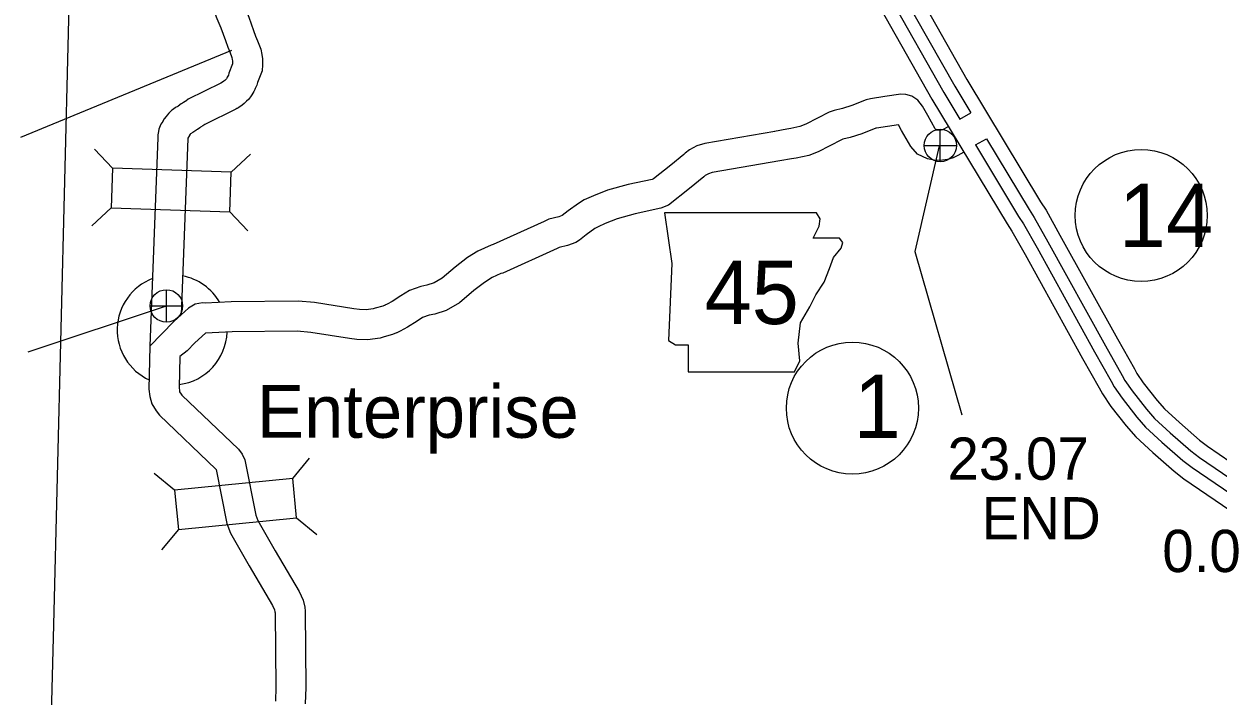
# Model space of a CAD drawing. Extents: x -939622 to -934245, y 1383184 to 1385301.
# Drawn here: x -936449.21 to -936413.38, y 1384508.29 to 1384528.45 of the extents above; entities that cross this region are included whole.
import ezdxf

# ---------------------------------------------------------------- set-up
doc = ezdxf.new("R2010")
doc.units = 0
for name, color, linetype in [('Level 1', 7, 'Continuous'), ('Level 10', 7, 'Continuous'), ('Level 15', 7, 'Continuous'), ('Level 20', 7, 'Continuous'), ('Level 21', 7, 'Continuous'), ('Level 24', 7, 'Continuous'), ('Level 25', 7, 'Continuous'), ('Level 26', 7, 'Continuous'), ('Level 27', 7, 'Continuous')]:
    doc.layers.add(name, color=color, linetype=linetype)

msp = doc.modelspace()

# ---------------------------------------------------------------- linework, layer by layer
at = {"layer": 'Level 1'}
for points in [[(-936448.314, 1384510.423), (-936447.763, 1384532.629)], [(-936449.208, 1384475.592), (-936449.172, 1384477.157), (-936448.921, 1384487.173), (-936448.696, 1384495.463), (-936448.314, 1384510.423)]]:
    msp.add_lwpolyline(points, dxfattribs=at)
at = {"layer": 'Level 10'}
for p, q in [((-936443.206, 1384526.735), (-936443.209, 1384526.732)), ((-936442.664, 1384526.016), (-936442.756, 1384525.946))]:
    msp.add_line(p, q, dxfattribs=at)
for points in [[(-936442.722, 1384529.313), (-936442.581, 1384528.946), (-936442.46, 1384528.649), (-936442.317, 1384528.252), (-936442.257, 1384528.079), (-936442.196, 1384527.944), (-936442.104, 1384527.69), (-936442.069, 1384527.528), (-936442.054, 1384527.4), (-936442.05, 1384527.223), (-936442.064, 1384527.044), (-936442.202, 1384526.693)], [(-936443.59, 1384529.063), (-936443.418, 1384528.615), (-936443.301, 1384528.327), (-936443.165, 1384527.951), (-936443.094, 1384527.747), (-936443.031, 1384527.606), (-936442.97, 1384527.44), (-936442.958, 1384527.382), (-936442.953, 1384527.338), (-936442.951, 1384527.249), (-936443.061, 1384526.967)], [(-936443.061, 1384526.967), (-936443.074, 1384526.914), (-936443.075, 1384526.913), (-936443.107, 1384526.852), (-936443.117, 1384526.824), (-936443.119, 1384526.821), (-936443.132, 1384526.803), (-936443.175, 1384526.759), (-936443.179, 1384526.755), (-936443.206, 1384526.735)], [(-936443.209, 1384526.732), (-936443.25, 1384526.701), (-936443.296, 1384526.675), (-936443.302, 1384526.671), (-936444.278, 1384526.194), (-936444.355, 1384526.129), (-936444.37, 1384526.12), (-936444.42, 1384526.091), (-936444.449, 1384526.068), (-936444.49, 1384526.048), (-936444.584, 1384525.983), (-936444.594, 1384525.975), (-936444.665, 1384525.943), (-936444.722, 1384525.889), (-936444.767, 1384525.861), (-936444.858, 1384525.775), (-936444.914, 1384525.708), (-936444.943, 1384525.672), (-936444.999, 1384525.602), (-936445.038, 1384525.528), (-936445.043, 1384525.519), (-936445.104, 1384525.439), (-936445.16, 1384525.293), (-936445.171, 1384525.226), (-936445.187, 1384525.123), (-936445.19, 1384525.044), (-936445.427, 1384518.784)], [(-936442.202, 1384526.693), (-936442.223, 1384526.607), (-936442.27, 1384526.511), (-936442.285, 1384526.482), (-936442.309, 1384526.419), (-936442.372, 1384526.319), (-936442.411, 1384526.264), (-936442.468, 1384526.184), (-936442.528, 1384526.134), (-936442.547, 1384526.114), (-936442.602, 1384526.063), (-936442.664, 1384526.016)], [(-936422.904, 1384526.343), (-936423.384, 1384526.272), (-936423.814, 1384526.206), (-936423.938, 1384526.173), (-936424.371, 1384525.998), (-936424.652, 1384525.909), (-936424.902, 1384525.855), (-936425.053, 1384525.798), (-936425.75, 1384525.437), (-936425.926, 1384525.369), (-936426.199, 1384525.309), (-936426.318, 1384525.293), (-936426.689, 1384525.225)], [(-936421.475, 1384525.372), (-936421.608, 1384525.296), (-936421.651, 1384525.276), (-936421.687, 1384525.266), (-936421.733, 1384525.259), (-936421.778, 1384525.257), (-936421.818, 1384525.265), (-936421.846, 1384525.278), (-936421.867, 1384525.301), (-936422.094, 1384525.699), (-936422.252, 1384525.979), (-936422.387, 1384526.158), (-936422.571, 1384526.277), (-936422.75, 1384526.328), (-936422.904, 1384526.343)], [(-936442.756, 1384525.946), (-936442.791, 1384525.925), (-936442.815, 1384525.913), (-936442.818, 1384525.912), (-936442.848, 1384525.891), (-936443.784, 1384525.434), (-936443.837, 1384525.389), (-936443.909, 1384525.347), (-936443.927, 1384525.333), (-936444.003, 1384525.284), (-936444.035, 1384525.268), (-936444.054, 1384525.255), (-936444.136, 1384525.193), (-936444.209, 1384525.148), (-936444.217, 1384525.139), (-936444.241, 1384525.108), (-936444.243, 1384525.106), (-936444.287, 1384525.026), (-936444.29, 1384525.022), (-936444.291, 1384525.012), (-936444.491, 1384519.725)], [(-936422.973, 1384525.424), (-936423.628, 1384525.324), (-936423.652, 1384525.318), (-936424.067, 1384525.151), (-936424.42, 1384525.039), (-936424.645, 1384524.99), (-936424.685, 1384524.974), (-936425.38, 1384524.615), (-936425.665, 1384524.505), (-936426.042, 1384524.422), (-936426.177, 1384524.403), (-936426.526, 1384524.339)], [(-936421.01, 1384524.601), (-936421.19, 1384524.499), (-936421.333, 1384524.43), (-936421.498, 1384524.384), (-936421.647, 1384524.361), (-936421.849, 1384524.353), (-936422.102, 1384524.404), (-936422.399, 1384524.543), (-936422.603, 1384524.775), (-936422.876, 1384525.254), (-936422.973, 1384525.424)], [(-936426.684, 1384525.225), (-936428.783, 1384524.864), (-936429.019, 1384524.787), (-936429.238, 1384524.674), (-936429.366, 1384524.575), (-936429.413, 1384524.528), (-936429.804, 1384524.215)], [(-936426.531, 1384524.338), (-936428.565, 1384523.989), (-936428.671, 1384523.954), (-936428.752, 1384523.912), (-936428.768, 1384523.9), (-936428.811, 1384523.857), (-936429.243, 1384523.512)], [(-936429.804, 1384524.215), (-936430.324, 1384523.8), (-936430.363, 1384523.785), (-936431.083, 1384523.631), (-936431.698, 1384523.457), (-936432.116, 1384523.293), (-936432.397, 1384523.168), (-936432.571, 1384523.065), (-936432.882, 1384522.844), (-936433.056, 1384522.703), (-936433.158, 1384522.666), (-936433.463, 1384522.593), (-936433.599, 1384522.523), (-936435.133, 1384521.829), (-936435.189, 1384521.817), (-936435.588, 1384521.632), (-936435.896, 1384521.439), (-936436.273, 1384521.156), (-936436.661, 1384520.821), (-936436.899, 1384520.685), (-936437.117, 1384520.616), (-936437.303, 1384520.574), (-936437.645, 1384520.454), (-936437.897, 1384520.292), (-936438.157, 1384520.124), (-936438.314, 1384520.039), (-936438.379, 1384520.011)], [(-936429.243, 1384523.512), (-936429.866, 1384523.014), (-936430.1, 1384522.921), (-936430.866, 1384522.757), (-936431.411, 1384522.603), (-936431.769, 1384522.463), (-936431.983, 1384522.367), (-936432.08, 1384522.31), (-936432.337, 1384522.127), (-936432.544, 1384521.959), (-936432.655, 1384521.891), (-936432.899, 1384521.803), (-936433.148, 1384521.743), (-936433.208, 1384521.712), (-936434.845, 1384520.972), (-936434.897, 1384520.96), (-936435.158, 1384520.839), (-936435.386, 1384520.696), (-936435.708, 1384520.455), (-936436.138, 1384520.084), (-936436.536, 1384519.855), (-936436.882, 1384519.747), (-936437.053, 1384519.708), (-936437.248, 1384519.639), (-936437.41, 1384519.535), (-936437.698, 1384519.35), (-936437.92, 1384519.229), (-936438.022, 1384519.185)], [(-936438.374, 1384520.013), (-936438.441, 1384519.985), (-936438.666, 1384519.924), (-936438.732, 1384519.901), (-936438.943, 1384519.871), (-936439.14, 1384519.878), (-936439.313, 1384519.901), (-936440.489, 1384520.089), (-936440.978, 1384520.133), (-936442.988, 1384520.112), (-936443.77, 1384520.075), (-936443.851, 1384520.08), (-936444.066, 1384520.042), (-936444.27, 1384519.926), (-936444.707, 1384519.528), (-936445.426, 1384518.784)], [(-936438.028, 1384519.183), (-936438.149, 1384519.132), (-936438.396, 1384519.065), (-936438.516, 1384519.022), (-936438.897, 1384518.969), (-936439.216, 1384518.98), (-936439.443, 1384519.01), (-936440.6, 1384519.195), (-936441.013, 1384519.232), (-936442.962, 1384519.212), (-936443.758, 1384519.175), (-936444.08, 1384518.882), (-936444.307, 1384518.647), (-936444.533, 1384518.47)], [(-936445.426, 1384518.784), (-936445.456, 1384517.497), (-936445.43, 1384517.274), (-936445.37, 1384517.056), (-936445.239, 1384516.842), (-936445.145, 1384516.716), (-936443.446, 1384515.098), (-936443.438, 1384515.087), (-936443.12, 1384513.467), (-936443.008, 1384513.173), (-936442.451, 1384512.197), (-936441.748, 1384511.003), (-936441.688, 1384510.875), (-936441.676, 1384510.817), (-936441.673, 1384510.787), (-936441.655, 1384508.554)], [(-936444.533, 1384518.47), (-936444.555, 1384517.54), (-936444.544, 1384517.445), (-936444.536, 1384517.417), (-936444.493, 1384517.347), (-936444.468, 1384517.314), (-936442.768, 1384515.695), (-936442.658, 1384515.546), (-936442.578, 1384515.377), (-936442.252, 1384513.716), (-936442.192, 1384513.558), (-936441.673, 1384512.649), (-936440.952, 1384511.425), (-936440.828, 1384511.163), (-936440.785, 1384510.955), (-936440.773, 1384510.838), (-936440.755, 1384508.547)], [(-936441.655, 1384508.554), (-936441.665, 1384508.14)], [(-936440.755, 1384508.547), (-936440.766, 1384508.053)]]:
    msp.add_lwpolyline(points, dxfattribs=at)
at = {"layer": 'Level 15'}
for points in [[(-936430.838, 1384544.304), (-936420.923, 1384526.779)], [(-936431.586, 1384543.189), (-936421.967, 1384526.188)], [(-936422.878, 1384529.398), (-936421.282, 1384526.576)], [(-936423.222, 1384529.243), (-936421.608, 1384526.392)], [(-936421.282, 1384526.576), (-936420.8, 1384525.777)], [(-936420.923, 1384526.779), (-936418.709, 1384523.107), (-936418.546, 1384522.86), (-936418.127, 1384522.112), (-936416.404, 1384518.999), (-936415.894, 1384518.104), (-936415.824, 1384517.967), (-936415.632, 1384517.688), (-936415.216, 1384517.158), (-936414.992, 1384516.903), (-936414.545, 1384516.491), (-936413.94, 1384515.966), (-936413.7, 1384515.78), (-936411.6, 1384514.349), (-936408.793, 1384512.149)], [(-936421.967, 1384526.188), (-936419.713, 1384522.45), (-936419.571, 1384522.235), (-936419.175, 1384521.528), (-936417.45, 1384518.412), (-936416.95, 1384517.533), (-936416.856, 1384517.35), (-936416.598, 1384516.976), (-936416.14, 1384516.392), (-936415.853, 1384516.064), (-936415.344, 1384515.596), (-936414.702, 1384515.039), (-936414.407, 1384514.809), (-936412.308, 1384513.379), (-936409.509, 1384511.185)], [(-936421.608, 1384526.392), (-936421.127, 1384525.593)], [(-936421.127, 1384525.593), (-936420.8, 1384525.777)], [(-936420.662, 1384524.822), (-936420.335, 1384525.006)], [(-936420.335, 1384525.006), (-936419.054, 1384522.881), (-936418.898, 1384522.645), (-936418.487, 1384521.911), (-936416.763, 1384518.797), (-936416.257, 1384517.907), (-936416.179, 1384517.755), (-936415.964, 1384517.443), (-936415.533, 1384516.895), (-936415.288, 1384516.614), (-936414.819, 1384516.183), (-936414.202, 1384515.647), (-936413.943, 1384515.446), (-936411.843, 1384514.015), (-936409.039, 1384511.818)], [(-936420.662, 1384524.822), (-936419.368, 1384522.675), (-936419.219, 1384522.45), (-936418.815, 1384521.729), (-936417.09, 1384518.614), (-936416.587, 1384517.729), (-936416.501, 1384517.562), (-936416.266, 1384517.221), (-936415.822, 1384516.656), (-936415.557, 1384516.352), (-936415.069, 1384515.904), (-936414.44, 1384515.357), (-936414.164, 1384515.143), (-936412.065, 1384513.713), (-936409.263, 1384511.517)]]:
    msp.add_lwpolyline(points, dxfattribs=at)
at = {"layer": 'Level 20'}
for p, q in [((-936446.552, 1384524.117), (-936447.094, 1384524.695)), ((-936442.99, 1384524.004), (-936442.413, 1384524.546)), ((-936446.59, 1384522.93), (-936447.168, 1384522.388)), ((-936443.028, 1384522.816), (-936442.486, 1384522.239)), ((-936441.145, 1384514.816), (-936440.642, 1384515.428)), ((-936444.691, 1384514.466), (-936445.304, 1384514.968)), ((-936441.028, 1384513.634), (-936440.416, 1384513.131)), ((-936444.575, 1384513.284), (-936445.077, 1384512.671))]:
    msp.add_line(p, q, dxfattribs=at)
for points in [[(-936446.59, 1384522.93), (-936443.028, 1384522.816), (-936442.99, 1384524.004), (-936446.552, 1384524.117)], [(-936444.575, 1384513.284), (-936441.028, 1384513.634), (-936441.145, 1384514.816), (-936444.691, 1384514.466)]]:
    msp.add_lwpolyline(points, close=True, dxfattribs=at)
at = {"layer": 'Level 21'}
msp.add_lwpolyline([(-936449.3, 1384525.047), (-936442.972, 1384527.661)], dxfattribs=at)
msp.add_lwpolyline([(-936429.994, 1384522.784), (-936429.766, 1384521.261), (-936429.867, 1384518.952), (-936429.664, 1384518.825), (-936429.283, 1384518.825), (-936429.283, 1384518.013), (-936426.086, 1384518.013), (-936425.934, 1384518.343), (-936425.984, 1384518.876), (-936425.908, 1384519.485), (-936425.629, 1384519.967), (-936425.452, 1384520.322), (-936425.198, 1384520.703), (-936425.045, 1384521.109), (-936424.919, 1384521.439), (-936424.69, 1384521.718), (-936424.639, 1384521.896), (-936424.741, 1384522.023), (-936425.528, 1384522.023), (-936425.35, 1384522.378), (-936425.325, 1384522.606), (-936425.43, 1384522.782)], close=True, dxfattribs=at)
at = {"layer": 'Level 24'}
for start, end in [(110.9363, 245.3145), (30.0451, 79.031), (277.2419, 357.759)]:
    msp.add_arc((-936444.76, 1384519.27), 1.65, start, end, dxfattribs=at)
at = {"layer": 'Level 25'}
msp.add_line((-936449.082, 1384518.61), (-936444.956, 1384519.985), dxfattribs=at)
msp.add_lwpolyline([(-936421.746, 1384524.789), (-936422.478, 1384521.623), (-936421.066, 1384516.727)], dxfattribs=at)
at = {"layer": 'Level 26'}
for p, q in [((-936421.716, 1384524.314), (-936421.716, 1384525.289)), ((-936422.204, 1384524.802), (-936421.229, 1384524.802)), ((-936444.933, 1384519.502), (-936444.933, 1384520.477)), ((-936445.421, 1384519.99), (-936444.446, 1384519.99))]:
    msp.add_line(p, q, dxfattribs=at)
for centre in [(-936421.716, 1384524.802), (-936444.933, 1384519.99)]:
    msp.add_circle(centre, 0.487, dxfattribs=at)
at = {"layer": 'Level 27'}
for centre in [(-936415.689, 1384522.704), (-936424.355, 1384516.927)]:
    msp.add_ellipse(centre, major_axis=(0, 1.98), ratio=0.999998, dxfattribs=at)

# ---------------------------------------------------------------- texts
at = {"layer": 'Level 21'}
msp.add_text('45', height=1.9008, dxfattribs=at).set_placement((-936428.789, 1384519.446))
at = {"layer": 'Level 24'}
msp.add_text('Enterprise', height=1.584, dxfattribs=at).set_placement((-936442.216, 1384516.035))
at = {"layer": 'Level 25'}
for s, p in [('23.07', (-936421.503, 1384514.777)), ('END', (-936420.48, 1384512.988)), ('0.0', (-936415.058, 1384512.008))]:
    msp.add_text(s, height=1.2672, dxfattribs=at).set_placement(p)
at = {"layer": 'Level 27'}
for s, height, p in [('14', 1.9008, (-936416.362, 1384521.754)), ('1', 1.901, (-936424.315, 1384516.032))]:
    msp.add_text(s, height=height, dxfattribs=at).set_placement(p)

doc.saveas('drawing.dxf')
